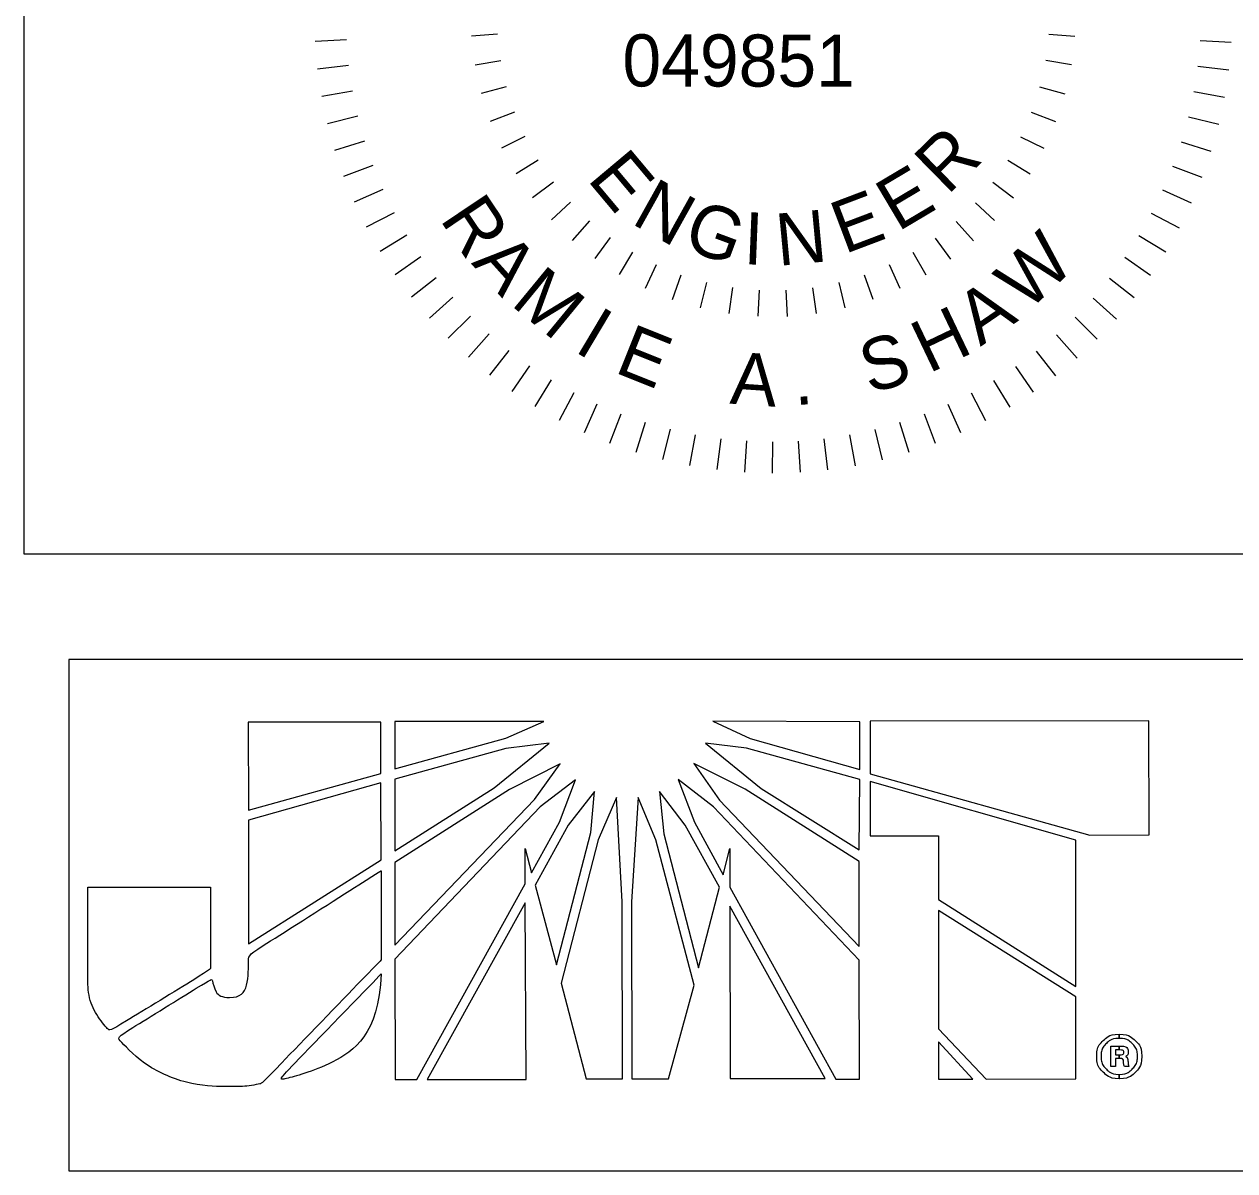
# Model space of a CAD drawing. Extents: x 2294455 to 2294842, y 719496 to 719941.
# Drawn here: x 2294735.35 to 2294756.72, y 719672.78 to 719693.01 of the extents above; entities that cross this region are included whole.
import ezdxf

# ---------------------------------------------------------------- set-up
doc = ezdxf.new("R2010")
doc.units = 0
for name, color, linetype in [('Default', 7, 'Continuous'), ('Old_Level_1', 7, 'Continuous'), ('Sheet Plan CELL', 7, 'Continuous')]:
    doc.layers.add(name, color=color, linetype=linetype)

msp = doc.modelspace()

# ---------------------------------------------------------------- linework, layer by layer
at = {"layer": 'Default'}
for p, q in [((2294740.49, 719692.713), (2294741.041, 719692.746)), ((2294743.251, 719692.812), (2294743.709, 719692.845)), ((2294753.9, 719692.797), (2294753.442, 719692.831)), ((2294756.66, 719692.69), (2294756.109, 719692.724)), ((2294740.534, 719692.226), (2294741.081, 719692.292)), ((2294743.313, 719692.3), (2294743.766, 719692.377)), ((2294753.386, 719692.379), (2294753.84, 719692.302)), ((2294756.615, 719692.203), (2294756.068, 719692.27)), ((2294743.423, 719691.795), (2294743.866, 719691.916)), ((2294753.725, 719691.781), (2294753.282, 719691.902)), ((2294740.606, 719691.742), (2294741.149, 719691.841)), ((2294756.541, 719691.72), (2294755.999, 719691.82)), ((2294743.582, 719691.305), (2294744.012, 719691.467)), ((2294753.565, 719691.291), (2294753.135, 719691.454)), ((2294740.708, 719691.264), (2294741.244, 719691.395)), ((2294756.438, 719691.242), (2294755.902, 719691.374)), ((2294743.787, 719690.832), (2294744.199, 719691.036)), ((2294753.358, 719690.819), (2294752.946, 719691.023)), ((2294740.839, 719690.792), (2294741.367, 719690.955)), ((2294756.306, 719690.77), (2294755.778, 719690.935)), ((2294744.037, 719690.381), (2294744.428, 719690.623)), ((2294753.107, 719690.368), (2294752.716, 719690.611)), ((2294740.998, 719690.33), (2294741.515, 719690.525)), ((2294756.146, 719690.308), (2294755.63, 719690.505)), ((2294744.329, 719689.955), (2294744.696, 719690.234)), ((2294752.813, 719689.943), (2294752.448, 719690.223)), ((2294741.185, 719689.878), (2294741.689, 719690.103)), ((2294755.957, 719689.857), (2294755.454, 719690.083)), ((2294744.662, 719689.561), (2294744.999, 719689.873)), ((2294752.48, 719689.55), (2294752.144, 719689.863)), ((2294741.398, 719689.437), (2294741.888, 719689.693)), ((2294745.03, 719689.2), (2294745.336, 719689.544)), ((2294752.111, 719689.19), (2294751.806, 719689.535)), ((2294755.743, 719689.417), (2294755.254, 719689.674)), ((2294741.638, 719689.01), (2294742.111, 719689.296)), ((2294745.432, 719688.877), (2294745.703, 719689.249)), ((2294751.708, 719688.868), (2294751.438, 719689.24)), ((2294755.502, 719688.99), (2294755.03, 719689.277)), ((2294741.903, 719688.599), (2294742.358, 719688.912)), ((2294745.863, 719688.594), (2294746.097, 719688.99)), ((2294751.276, 719688.586), (2294751.043, 719688.983)), ((2294755.236, 719688.58), (2294754.782, 719688.895)), ((2294746.32, 719688.353), (2294746.514, 719688.771)), ((2294750.818, 719688.347), (2294750.625, 719688.765)), ((2294742.192, 719688.205), (2294742.627, 719688.545)), ((2294746.797, 719688.158), (2294746.951, 719688.592)), ((2294747.399, 719688.457), (2294747.288, 719688.01)), ((2294749.846, 719688.006), (2294749.736, 719688.453)), ((2294750.34, 719688.153), (2294750.188, 719688.587)), ((2294754.945, 719688.187), (2294754.511, 719688.528)), ((2294747.797, 719687.91), (2294747.864, 719688.365)), ((2294748.311, 719687.859), (2294748.333, 719688.319)), ((2294748.826, 719687.858), (2294748.805, 719688.318)), ((2294749.339, 719687.908), (2294749.274, 719688.363)), ((2294742.506, 719687.828), (2294742.919, 719688.194)), ((2294754.631, 719687.811), (2294754.219, 719688.178)), ((2294742.84, 719687.472), (2294743.231, 719687.862)), ((2294754.295, 719687.456), (2294753.906, 719687.846)), ((2294743.196, 719687.136), (2294743.563, 719687.548)), ((2294753.939, 719687.121), (2294753.573, 719687.534)), ((2294743.572, 719686.822), (2294743.912, 719687.256)), ((2294753.562, 719686.808), (2294753.223, 719687.243)), ((2294743.965, 719686.532), (2294744.279, 719686.985)), ((2294753.168, 719686.519), (2294752.855, 719686.973)), ((2294744.375, 719686.265), (2294744.662, 719686.737)), ((2294752.757, 719686.253), (2294752.471, 719686.726)), ((2294744.801, 719686.024), (2294745.059, 719686.513)), ((2294745.241, 719685.81), (2294745.468, 719686.313)), ((2294751.889, 719685.801), (2294751.664, 719686.304)), ((2294752.33, 719686.013), (2294752.074, 719686.503)), ((2294745.693, 719685.621), (2294745.89, 719686.138)), ((2294751.437, 719685.613), (2294751.242, 719686.13)), ((2294746.155, 719685.461), (2294746.32, 719685.989)), ((2294750.975, 719685.454), (2294750.812, 719685.982)), ((2294746.627, 719685.329), (2294746.759, 719685.865)), ((2294747.105, 719685.226), (2294747.205, 719685.768)), ((2294747.588, 719685.152), (2294747.655, 719685.699)), ((2294748.075, 719685.107), (2294748.109, 719685.658)), ((2294749.054, 719685.105), (2294749.021, 719685.656)), ((2294749.541, 719685.149), (2294749.475, 719685.697)), ((2294750.025, 719685.221), (2294749.926, 719685.765)), ((2294750.503, 719685.323), (2294750.372, 719685.86)), ((2294748.564, 719685.091), (2294748.565, 719685.643))]:
    msp.add_line(p, q, dxfattribs=at)
at = {"layer": 'Old_Level_1'}
for p, q in [((2294741.651, 719680.695), (2294739.31, 719680.693)), ((2294739.31, 719680.693), (2294739.312, 719679.14)), ((2294741.652, 719679.791), (2294741.651, 719680.695)), ((2294744.528, 719680.709), (2294741.894, 719680.707)), ((2294741.894, 719680.707), (2294741.895, 719679.869)), ((2294743.856, 719680.411), (2294744.528, 719680.709)), ((2294750.104, 719680.703), (2294747.509, 719680.712)), ((2294747.509, 719680.712), (2294748.166, 719680.404)), ((2294750.105, 719679.861), (2294750.104, 719680.703)), ((2294755.206, 719680.72), (2294750.286, 719680.715)), ((2294750.286, 719680.715), (2294750.287, 719679.811)), ((2294755.208, 719678.704), (2294755.206, 719680.72)), ((2294741.895, 719679.869), (2294743.856, 719680.411)), ((2294743.652, 719679.535), (2294744.621, 719680.323)), ((2294744.621, 719680.323), (2294743.856, 719680.23)), ((2294747.378, 719680.326), (2294748.36, 719679.524)), ((2294748.101, 719680.234), (2294747.378, 719680.326)), ((2294748.166, 719680.404), (2294750.105, 719679.861)), ((2294743.856, 719680.23), (2294741.895, 719679.687)), ((2294750.105, 719679.684), (2294748.101, 719680.234)), ((2294744.814, 719679.961), (2294743.923, 719679.508)), ((2294744.363, 719679.327), (2294744.814, 719679.961)), ((2294747.174, 719679.963), (2294747.627, 719679.318)), ((2294748.078, 719679.512), (2294747.174, 719679.963)), ((2294739.312, 719679.14), (2294741.652, 719679.791)), ((2294741.895, 719679.687), (2294741.896, 719678.421)), ((2294745.085, 719679.679), (2294744.464, 719679.199)), ((2294744.8, 719678.929), (2294745.085, 719679.679)), ((2294746.9, 719679.681), (2294747.187, 719678.932)), ((2294747.522, 719679.202), (2294746.9, 719679.681)), ((2294750.091, 719678.444), (2294750.105, 719679.684)), ((2294750.287, 719679.811), (2294750.287, 719679.784)), ((2294750.287, 719679.784), (2294754.161, 719678.703)), ((2294741.652, 719679.622), (2294739.312, 719678.963)), ((2294741.653, 719678.266), (2294741.652, 719679.622)), ((2294741.896, 719678.421), (2294743.652, 719679.535)), ((2294743.923, 719679.508), (2294741.896, 719678.216)), ((2294745.421, 719679.471), (2294744.958, 719678.875)), ((2294745.356, 719678.748), (2294745.421, 719679.471)), ((2294746.568, 719679.472), (2294746.646, 719678.723)), ((2294747.021, 719678.877), (2294746.568, 719679.472)), ((2294750.091, 719678.235), (2294748.078, 719679.512)), ((2294748.36, 719679.524), (2294750.091, 719678.444)), ((2294750.287, 719679.645), (2294750.287, 719679.63)), ((2294753.914, 719678.614), (2294750.287, 719679.645)), ((2294750.287, 719679.63), (2294750.288, 719678.687)), ((2294741.898, 719676.756), (2294744.363, 719679.327)), ((2294745.807, 719679.367), (2294745.488, 719678.617)), ((2294745.91, 719677.521), (2294745.807, 719679.367)), ((2294746.194, 719679.367), (2294746.076, 719677.521)), ((2294746.503, 719678.618), (2294746.194, 719679.367)), ((2294747.627, 719679.318), (2294750.093, 719676.737)), ((2294744.464, 719679.199), (2294741.898, 719676.509)), ((2294750.093, 719676.494), (2294747.522, 719679.202)), ((2294739.312, 719678.963), (2294739.314, 719676.781)), ((2294744.31, 719678.037), (2294744.8, 719678.929)), ((2294744.958, 719678.875), (2294744.376, 719677.817)), ((2294747.628, 719677.781), (2294747.021, 719678.877)), ((2294747.187, 719678.932), (2294747.69, 719678.001)), ((2294744.752, 719676.411), (2294745.356, 719678.748)), ((2294745.488, 719678.617), (2294744.83, 719676.087)), ((2294747.178, 719676.051), (2294746.503, 719678.618)), ((2294746.646, 719678.723), (2294747.255, 719676.36)), ((2294750.288, 719678.687), (2294751.489, 719678.689)), ((2294751.489, 719678.689), (2294751.49, 719677.565)), ((2294753.917, 719676.03), (2294753.914, 719678.614)), ((2294754.161, 719678.703), (2294755.208, 719678.704)), ((2294744.195, 719677.844), (2294744.194, 719678.462)), ((2294744.194, 719678.462), (2294744.31, 719678.037)), ((2294747.69, 719678.001), (2294747.809, 719678.465)), ((2294747.809, 719678.465), (2294747.809, 719677.781)), ((2294739.314, 719676.781), (2294741.653, 719678.266)), ((2294741.896, 719678.216), (2294741.898, 719676.756)), ((2294750.093, 719676.737), (2294750.091, 719678.235)), ((2294742.286, 719674.385), (2294744.195, 719677.844)), ((2294744.376, 719677.817), (2294744.752, 719676.411)), ((2294747.255, 719676.36), (2294747.628, 719677.781)), ((2294747.809, 719677.781), (2294749.682, 719674.393)), ((2294751.49, 719677.565), (2294753.917, 719676.03)), ((2294744.195, 719677.508), (2294742.468, 719674.386)), ((2294744.213, 719674.387), (2294744.195, 719677.508)), ((2294745.913, 719674.4), (2294745.91, 719677.521)), ((2294746.076, 719677.521), (2294746.079, 719674.401)), ((2294749.489, 719674.404), (2294747.81, 719677.445)), ((2294747.81, 719677.445), (2294747.813, 719674.402)), ((2294751.49, 719677.372), (2294751.492, 719675.279)), ((2294753.917, 719675.849), (2294751.49, 719677.372)), ((2294741.898, 719676.509), (2294741.9, 719674.385)), ((2294750.095, 719674.393), (2294750.093, 719676.494)), ((2294744.83, 719676.087), (2294745.272, 719674.4)), ((2294746.727, 719674.401), (2294747.178, 719676.051)), ((2294753.918, 719674.397), (2294753.917, 719675.849)), ((2294751.492, 719675.279), (2294752.331, 719674.395)), ((2294754.68, 719675.187), (2294754.68, 719675.113)), ((2294754.68, 719675.113), (2294754.68, 719675.187)), ((2294752.099, 719674.395), (2294751.492, 719675.051)), ((2294751.492, 719675.051), (2294751.493, 719674.394)), ((2294754.534, 719674.618), (2294754.534, 719674.976)), ((2294754.534, 719674.976), (2294754.68, 719674.976)), ((2294754.68, 719674.976), (2294754.68, 719674.908)), ((2294754.68, 719674.908), (2294754.68, 719674.976)), ((2294754.68, 719674.976), (2294754.703, 719674.976)), ((2294754.68, 719674.908), (2294754.615, 719674.908)), ((2294754.615, 719674.908), (2294754.615, 719674.823)), ((2294754.615, 719674.823), (2294754.68, 719674.823)), ((2294754.681, 719674.758), (2294754.616, 719674.758)), ((2294754.616, 719674.758), (2294754.616, 719674.618)), ((2294754.69, 719674.908), (2294754.68, 719674.908)), ((2294754.68, 719674.823), (2294754.681, 719674.758)), ((2294754.681, 719674.758), (2294754.68, 719674.823)), ((2294754.68, 719674.823), (2294754.684, 719674.823)), ((2294754.684, 719674.758), (2294754.681, 719674.758)), ((2294754.616, 719674.618), (2294754.534, 719674.618)), ((2294741.9, 719674.385), (2294742.286, 719674.385)), ((2294742.468, 719674.386), (2294744.213, 719674.387)), ((2294745.272, 719674.4), (2294745.913, 719674.4)), ((2294746.079, 719674.401), (2294746.727, 719674.401)), ((2294747.813, 719674.402), (2294749.489, 719674.404)), ((2294749.682, 719674.393), (2294750.095, 719674.393)), ((2294751.493, 719674.394), (2294752.099, 719674.395)), ((2294752.331, 719674.395), (2294753.918, 719674.397)), ((2294754.681, 719674.478), (2294754.681, 719674.4)), ((2294754.681, 719674.4), (2294754.681, 719674.478)), ((2294754.681, 719674.478), (2294754.684, 719674.478)), ((2294754.684, 719674.4), (2294754.681, 719674.4))]:
    msp.add_line(p, q, dxfattribs=at)
msp.add_lwpolyline([(2294736.145, 719672.776), (2294786.155, 719672.776), (2294786.155, 719681.8), (2294736.145, 719681.8)], close=True, dxfattribs=at)
for points in [[(2294739.312, 719679.14), (2294741.652, 719679.791), (2294741.651, 719680.695), (2294739.31, 719680.693), (2294739.312, 719679.14)], [(2294743.856, 719680.411), (2294744.528, 719680.709), (2294741.894, 719680.707), (2294741.895, 719679.869), (2294743.856, 719680.411)], [(2294748.166, 719680.404), (2294750.105, 719679.861), (2294750.104, 719680.703), (2294747.509, 719680.712), (2294748.166, 719680.404)], [(2294755.206, 719680.72), (2294750.286, 719680.715), (2294750.287, 719679.811), (2294750.287, 719679.784), (2294754.161, 719678.703), (2294755.208, 719678.704), (2294755.206, 719680.72)], [(2294741.895, 719679.687), (2294741.896, 719678.421), (2294743.652, 719679.535), (2294744.621, 719680.323), (2294743.856, 719680.23), (2294741.895, 719679.687)], [(2294747.378, 719680.326), (2294748.36, 719679.524), (2294750.091, 719678.444), (2294750.105, 719679.684), (2294748.101, 719680.234), (2294747.378, 719680.326)], [(2294741.896, 719678.216), (2294741.898, 719676.756), (2294744.363, 719679.327), (2294744.814, 719679.961), (2294743.923, 719679.508), (2294741.896, 719678.216)], [(2294747.174, 719679.963), (2294747.627, 719679.318), (2294750.093, 719676.737), (2294750.091, 719678.235), (2294748.078, 719679.512), (2294747.174, 719679.963)], [(2294745.085, 719679.679), (2294744.464, 719679.199), (2294741.898, 719676.509), (2294741.9, 719674.385), (2294742.286, 719674.385), (2294744.195, 719677.844), (2294744.194, 719678.462), (2294744.31, 719678.037), (2294744.8, 719678.929), (2294745.085, 719679.679)], [(2294746.9, 719679.681), (2294747.187, 719678.932), (2294747.69, 719678.001), (2294747.809, 719678.465), (2294747.809, 719677.781), (2294749.682, 719674.393), (2294750.095, 719674.393), (2294750.093, 719676.494), (2294747.522, 719679.202), (2294746.9, 719679.681)], [(2294739.314, 719676.781), (2294741.653, 719678.266), (2294741.652, 719679.622), (2294739.312, 719678.963), (2294739.314, 719676.781)], [(2294745.421, 719679.471), (2294744.958, 719678.875), (2294744.376, 719677.817), (2294744.752, 719676.411), (2294745.356, 719678.748), (2294745.421, 719679.471)], [(2294746.568, 719679.472), (2294746.646, 719678.723), (2294747.255, 719676.36), (2294747.628, 719677.781), (2294747.021, 719678.877), (2294746.568, 719679.472)], [(2294750.287, 719679.645), (2294750.287, 719679.63), (2294750.288, 719678.687), (2294751.489, 719678.689), (2294751.49, 719677.565), (2294753.917, 719676.03), (2294753.914, 719678.614), (2294750.287, 719679.645)], [(2294745.488, 719678.617), (2294744.83, 719676.087), (2294745.272, 719674.4), (2294745.913, 719674.4), (2294745.91, 719677.521), (2294745.807, 719679.367), (2294745.488, 719678.617)], [(2294746.194, 719679.367), (2294746.076, 719677.521), (2294746.079, 719674.401), (2294746.727, 719674.401), (2294747.178, 719676.051), (2294746.503, 719678.618), (2294746.194, 719679.367)], [(2294742.468, 719674.386), (2294744.213, 719674.387), (2294744.195, 719677.508), (2294742.468, 719674.386)], [(2294747.813, 719674.402), (2294749.489, 719674.404), (2294747.81, 719677.445), (2294747.813, 719674.402)], [(2294751.49, 719677.372), (2294751.492, 719675.279), (2294752.331, 719674.395), (2294753.918, 719674.397), (2294753.917, 719675.849), (2294751.49, 719677.372), (2294751.49, 719677.372)], [(2294751.493, 719674.394), (2294751.493, 719674.394), (2294752.099, 719674.395), (2294751.492, 719675.051), (2294751.493, 719674.394)], [(2294754.837, 719674.703), (2294754.837, 719674.683), (2294754.84, 719674.67), (2294754.84, 719674.657), (2294754.85, 719674.618), (2294754.775, 719674.618)]]:
    msp.add_lwpolyline(points, dxfattribs=at)
for points, degree in [([(2294738.979, 719675.834), (2294738.84, 719675.834), (2294738.72, 719675.911), (2294738.67, 719676.17), (2294738.67, 719676.17), (2294736.991, 719675.13), (2294736.991, 719675.13), (2294737.509, 719674.586), (2294738.336, 719674.262), (2294739.035, 719674.263), (2294739.216, 719674.263), (2294739.355, 719674.278), (2294739.548, 719674.317), (2294739.548, 719674.317), (2294741.655, 719676.497), (2294741.655, 719676.497), (2294741.655, 719676.497), (2294741.653, 719678.073), (2294741.653, 719678.073), (2294741.653, 719678.073), (2294739.314, 719676.584), (2294739.314, 719676.584), (2294739.315, 719675.993), (2294739.172, 719675.835), (2294738.979, 719675.834)], 3), ([(2294738.979, 719675.834), (2294738.84, 719675.834), (2294738.72, 719675.911), (2294738.67, 719676.17), (2294738.67, 719676.17), (2294736.991, 719675.13), (2294736.991, 719675.13), (2294737.509, 719674.586), (2294738.336, 719674.262), (2294739.035, 719674.263), (2294739.216, 719674.263), (2294739.355, 719674.278), (2294739.548, 719674.317), (2294739.548, 719674.317), (2294741.655, 719676.497), (2294741.655, 719676.497), (2294741.655, 719676.497), (2294741.653, 719678.073), (2294741.653, 719678.073), (2294741.653, 719678.073), (2294739.314, 719676.584), (2294739.314, 719676.584), (2294739.315, 719675.993), (2294739.172, 719675.835), (2294738.979, 719675.834)], 3), ([(2294738.641, 719677.784), (2294738.641, 719677.784), (2294736.475, 719677.782), (2294736.475, 719677.782), (2294736.475, 719677.782), (2294736.476, 719676.427), (2294736.476, 719676.427), (2294736.476, 719676.427), (2294736.476, 719676.284), (2294736.476, 719676.284), (2294736.477, 719675.859), (2294736.616, 719675.523), (2294736.863, 719675.241), (2294736.863, 719675.241), (2294738.643, 719676.325), (2294738.643, 719676.352), (2294738.643, 719676.352), (2294738.641, 719677.784), (2294738.641, 719677.784)], 3), ([(2294741.655, 719676.25), (2294741.655, 719676.25), (2294739.834, 719674.368), (2294739.834, 719674.368), (2294740.726, 719674.589), (2294741.614, 719675.18), (2294741.655, 719676.25)], 3), ([(2294754.681, 719674.4), (2294754.574, 719674.4), (2294754.479, 719674.439), (2294754.401, 719674.517), (2294754.323, 719674.592), (2294754.284, 719674.686), (2294754.284, 719674.797), (2294754.284, 719674.907), (2294754.323, 719675.002), (2294754.401, 719675.073), (2294754.479, 719675.148), (2294754.57, 719675.187), (2294754.68, 719675.187)], 3), ([(2294754.68, 719675.187), (2294754.791, 719675.187), (2294754.885, 719675.149), (2294754.963, 719675.074), (2294755.041, 719675.002), (2294755.081, 719674.908), (2294755.081, 719674.797)], 3), ([(2294754.68, 719675.113), (2294754.592, 719675.112), (2294754.518, 719675.083), (2294754.456, 719675.024), (2294754.394, 719674.963), (2294754.362, 719674.885), (2294754.362, 719674.797), (2294754.362, 719674.709), (2294754.394, 719674.631), (2294754.456, 719674.569), (2294754.518, 719674.507), (2294754.593, 719674.478), (2294754.681, 719674.478)], 3), ([(2294754.684, 719674.478), (2294754.772, 719674.478), (2294754.847, 719674.508), (2294754.908, 719674.57), (2294754.97, 719674.631), (2294755.003, 719674.71), (2294755.003, 719674.797), (2294755.002, 719674.885), (2294754.97, 719674.963), (2294754.908, 719675.025), (2294754.846, 719675.083), (2294754.771, 719675.113), (2294754.68, 719675.113)], 3), ([(2294754.703, 719674.976), (2294754.794, 719674.976), (2294754.84, 719674.94), (2294754.84, 719674.869), (2294754.84, 719674.836), (2294754.827, 719674.81), (2294754.798, 719674.791)], 3), ([(2294754.684, 719674.823), (2294754.736, 719674.823), (2294754.762, 719674.839), (2294754.762, 719674.869), (2294754.762, 719674.895), (2294754.739, 719674.908), (2294754.69, 719674.908)], 3), ([(2294755.081, 719674.797), (2294755.081, 719674.687), (2294755.042, 719674.593), (2294754.967, 719674.514), (2294754.889, 719674.439), (2294754.795, 719674.4), (2294754.684, 719674.4)], 3), ([(2294754.746, 719674.745), (2294754.736, 719674.752), (2294754.716, 719674.758), (2294754.684, 719674.758)], 2), ([(2294754.798, 719674.791), (2294754.82, 719674.778), (2294754.833, 719674.748), (2294754.837, 719674.703)], 2), ([(2294754.775, 719674.618), (2294754.765, 719674.638), (2294754.759, 719674.657), (2294754.759, 719674.683), (2294754.759, 719674.716), (2294754.755, 719674.735), (2294754.746, 719674.745)], 3)]:
    msp.add_open_spline(points, degree=degree, dxfattribs=at)
at = {"layer": 'Sheet Plan CELL'}
msp.add_lwpolyline([(2294761.64, 719683.659), (2294735.355, 719683.659), (2294735.355, 719706.159), (2294761.64, 719706.159)], dxfattribs=at)

# ---------------------------------------------------------------- texts
at = {"layer": 'Default'}
for s, height, rotation, p in [('049851', 0.9194, 359.9186, (2294745.913, 719691.917)), ('R', 0.94, 44.4835, (2294751.651, 719689.983)), ('E', 0.94, 309.9887, (2294745.276, 719690.276)), ('E', 0.934, 30.7124, (2294750.774, 719689.343)), ('N', 0.933, 330.8438, (2294746.047, 719689.508)), ('R', 0.938, 303.8537, (2294742.678, 719689.576)), ('E', 0.928, 20.7266, (2294749.83, 719688.952)), ('G', 0.927, 339.61, (2294746.947, 719689.076)), ('N', 0.92, 5.3345, (2294748.665, 719688.748)), ('I', 0.92, 357.7048, (2294748.041, 719688.78)), ('W', 0.94, 43.2431, (2294753.062, 719687.924)), ('A', 0.94, 311.9255, (2294743.235, 719688.795)), ('M', 0.939, 320.5682, (2294743.922, 719688.07)), ('A', 0.937, 34.3604, (2294752.231, 719687.319)), ('H', 0.931, 25.5378, (2294751.32, 719686.843)), ('I', 0.934, 329.2408, (2294745.04, 719687.253)), ('E', 0.928, 338.2133, (2294745.751, 719686.878)), ('S', 0.925, 16.5353, (2294750.272, 719686.486)), ('A', 0.92, 356.0086, (2294747.798, 719686.318)), ('.', 0.92, 3.7509, (2294748.955, 719686.29))]:
    msp.add_text(s, height=height, rotation=rotation, dxfattribs=at).set_placement(p)

doc.saveas('drawing.dxf')
